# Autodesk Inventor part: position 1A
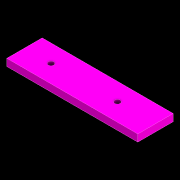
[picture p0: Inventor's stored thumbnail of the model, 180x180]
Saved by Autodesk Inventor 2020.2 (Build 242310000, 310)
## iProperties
Category: 1
Manager: PART
Company: 25
Created: 2020-10
Part Number: position 1A
Material: Generic
Document SubType Name: Modeling
Designer: Apardo
Density: 1 g/cm^3
Appearance: Magenta
Vendor: 1A
Project: PLATE ROLLING MACHINE
Cost Center: 1
Engineer: STEEL C45
Stock Number: 3.1
Engr Approved By: D. JAEGER
Author: Apardo
Revision Number: 1.0
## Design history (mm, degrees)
sketch "Sketch1"
  geometry: L1 (74, 20)-(-74, 20); L2 (-74, 20)-(-74, -20); L3 (-74, -20)-(74, -20); L4 (74, -20)-(74, 20); L5 (74, 20)-(-74, -20); L6 (-74, 20)-(74, -20); 1 further point
  constraints: 12 end point, 2 midpoint, 2 parallel, 1 horizontal, 1 perpendicular
  dimensions: "d0" = 148 distance of L2.end L3.end; "d1" = 40 distance of L3.end L1.start
extrude "Extrusion1" new body sketch "Sketch1" stored distance "d2" = 8; taper "d3" = 0 deg
sketch "Sketch2"
  geometry: L1 (-74, 20)-(-74, -20) reference; 3 further points
  constraints: 2 horizontal alignment
  dimensions: "d4" = 75 distance of point (31, 0) point (-44, 0); "d13" = 30 distance from line of L1 point (-44, 0)
hole "Hole1" sketch "Sketch2" at (-44, 0), (31, 0) diameter "d6" = 6.2; stored, may be unused: countersink angle "d10" = 90 deg, drill point angle "d12" = 118 deg; dims "d7" = 12, "d8" = 4, "d9" = 2, "d11" = 17.1
body "Solid1"
